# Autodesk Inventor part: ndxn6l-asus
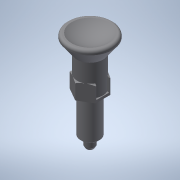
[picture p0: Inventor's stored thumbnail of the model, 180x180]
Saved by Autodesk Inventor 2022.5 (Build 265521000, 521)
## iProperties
Created: 2016-12
Part Number: ndxn6l-asus
Material: 一般
Document SubType Name: Modeling
Designer: imaocorp
Density: 1 g/cm^3
Appearance: 既定
Author: imaocorp
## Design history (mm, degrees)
node "ndxn6l-asus.x_t1"
node "ndxn6l-asus"
node "Base1"
